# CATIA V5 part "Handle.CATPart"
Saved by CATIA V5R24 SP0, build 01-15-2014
Part number: Handle
Bounding box of the stored display mesh (mm): x -5 to 5, y -5 to 5, z -70 to 70
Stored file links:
  C:\Users\minsi\Google 드라이브\CDL_2019\00_CLASS\00_CAD\기말고사\DMU\Handle.CATPart
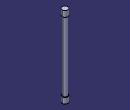
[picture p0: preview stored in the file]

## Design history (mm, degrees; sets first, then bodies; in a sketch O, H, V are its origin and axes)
Body1 (main body)
  Sketch1 on xy-plane, origin (0, 0, 0), H (1, 0, 0), V (0, 1, 0)
    circle A1 centre (0, 0) radius 4
    radius A1 = 4
  Pad1: profile Sketch1, direction (0, 0, 1), length 60, mirrored extent
  Sketch2 on end face of Pad1, origin (0, 0, 60), H (1, 0, 0), V (0, 1, 0)
    circle A1 centre (0, 0) radius 5
    radius A1 = 5
  Pad2: profile Sketch2, direction (0, 0, 1), length 10
  Mirror1: of Pad2, about xy-plane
